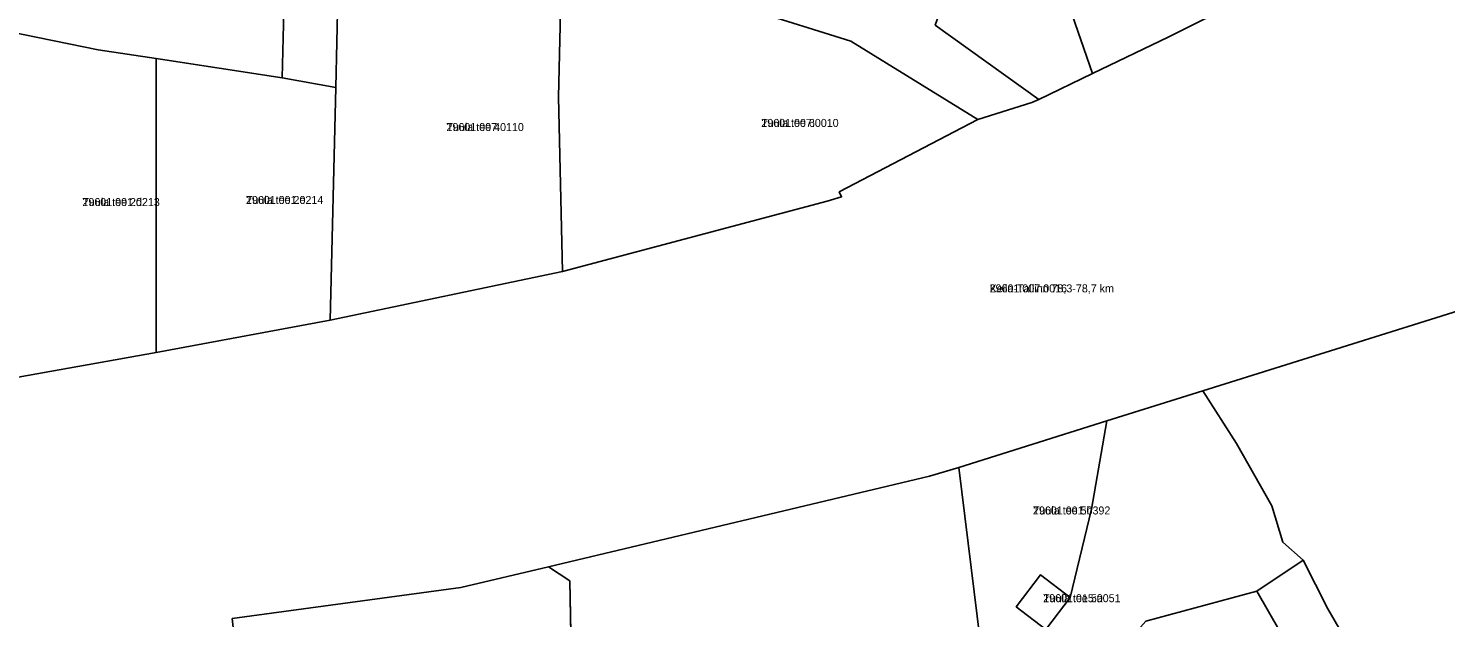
# Model space of a CAD drawing. Extents: x 518839 to 525192, y 6573164 to 6576561.
# Drawn here: x 524522.2 to 524787.8, y 6574299.5 to 6574409.9 of the extents above; entities that cross this region are included whole.
import ezdxf

# ---------------------------------------------------------------- set-up
doc = ezdxf.new("R2010")
doc.units = 0
for name, color, linetype in [('L_AADRESS', 7, 'Continuous'), ('PIIR', 7, 'Continuous'), ('TUNNUS', 7, 'Continuous')]:
    doc.layers.add(name, color=color, linetype=linetype)

msp = doc.modelspace()

# ---------------------------------------------------------------- linework, layer by layer
at = {"layer": 'PIIR'}
for points in [[(524710.7, 6574433.06), (524701.35, 6574436.41), (524703.48, 6574442.58), (524752.09, 6574425.48), (524753.73, 6574417.26), (524735.93, 6574408.31), (524721.62, 6574401.47)], [(524711.59, 6574396.58), (524692.17, 6574410.53), (524701.35, 6574436.41), (524710.7, 6574433.06), (524721.62, 6574401.47)], [(524569.76, 6574400.68), (524570.37, 6574425.69), (524580.41, 6574424.36), (524579.81, 6574398.82)], [(524578.79, 6574355.29), (524579.81, 6574398.82), (524580.41, 6574424.36), (524622.07, 6574418.51), (524621.56, 6574397.04), (524622.34, 6574364.41)], [(524676.36, 6574407.54), (524700.15, 6574392.87), (524674.19, 6574379.29), (524674.63, 6574378.38), (524671.89, 6574377.53), (524622.34, 6574364.41), (524621.56, 6574397.04), (524622.07, 6574418.51), (524657.52, 6574413.39)], [(524518.51, 6574344.28), (524518.5, 6574409.32), (524535.31, 6574405.91), (524546.16, 6574404.26), (524546.14, 6574349.24)], [(524546.14, 6574349.24), (524546.16, 6574404.26), (524569.76, 6574400.68), (524579.81, 6574398.82), (524578.79, 6574355.29)], [(524757.32, 6574313.68), (524755.25, 6574320.46), (524748.62, 6574332.15), (524742.33, 6574342), (524803.74, 6574361.26), (524817.51, 6574365.76), (524818.28, 6574363.86), (524819.99, 6574359.63), (524842.07, 6574311.36), (524849.11, 6574297.12), (524854.77, 6574284.94), (524848.11, 6574281.06), (524835.53, 6574272.95), (524827.49, 6574266.87), (524817.72, 6574259.66), (524804.86, 6574250.61), (524783.72, 6574275.28), (524771.53, 6574291.26), (524765.78, 6574301.17), (524761.13, 6574310.28)], [(524721.44, 6574319.86), (524717.46, 6574303.31), (524711.9, 6574307.56), (524707.37, 6574301.59), (524712.9, 6574297.35), (524702.91, 6574276.51), (524696.62, 6574327.69), (524724.36, 6574336.38)], [(524619.68, 6574309.06), (524691.12, 6574326.02), (524696.62, 6574327.69), (524702.91, 6574276.51), (524701.78, 6574241.63), (524655.29, 6574237.1), (524654.83, 6574244.98), (524646.53, 6574244.88), (524643.9, 6574280.19), (524634.74, 6574287.42), (524624.06, 6574286.46), (524623.93, 6574293.61), (524623.69, 6574306.41)], [(524560.4, 6574299.4), (524603.25, 6574305.18), (524619.68, 6574309.06), (524623.69, 6574306.41), (524624.06, 6574286.46), (524624.27, 6574279.16), (524604.1, 6574276.92), (524605.36, 6574232.04), (524568.45, 6574228.15)], [(524752.47, 6574304.49), (524761.13, 6574310.28), (524765.78, 6574301.17), (524771.53, 6574291.26), (524783.72, 6574275.28), (524804.86, 6574250.61), (524796.76, 6574244.54), (524775.96, 6574268.97), (524763.38, 6574285.46)], [(524711.9, 6574307.56), (524717.46, 6574303.31), (524712.9, 6574297.35), (524707.37, 6574301.59)], [(524758.45, 6574075.08), (524685.85, 6574091.49), (524706.65, 6574149.93), (524716.14, 6574215.55), (524718.22, 6574259.84), (524722.06, 6574288.12), (524731.67, 6574298.88), (524752.47, 6574304.49), (524763.38, 6574285.46), (524763.94, 6574247.94), (524757.99, 6574233.52), (524759.38, 6574223.94), (524761.69, 6574212.15), (524769.27, 6574204.08), (524773.19, 6574198.81), (524777.2, 6574186.81), (524780.96, 6574174.13), (524779.67, 6574161.43), (524773.36, 6574149), (524767.67, 6574140.07), (524757.52, 6574134.15), (524742.35, 6574126.62), (524728.14, 6574113.06), (524743.84, 6574093.15)]]:
    msp.add_lwpolyline(points, close=True, dxfattribs=at)
for points in [[(524377.78, 6574286.88), (524374.42, 6574333.78), (524391.22, 6574334.37), (524426.7, 6574335.33), (524449.29, 6574335.16), (524459.67, 6574335.09), (524482.48, 6574337.78), (524490.84, 6574339.28), (524518.51, 6574344.28), (524546.14, 6574349.24), (524578.79, 6574355.29), (524622.34, 6574364.41), (524671.89, 6574377.53), (524674.63, 6574378.38), (524674.19, 6574379.29), (524700.15, 6574392.87), (524710.26, 6574396.01), (524711.59, 6574396.58), (524721.62, 6574401.47), (524735.93, 6574408.31), (524753.73, 6574417.26), (524778.37, 6574429.72), (524790.19, 6574434.06)], [(524570.37, 6574425.69), (524569.76, 6574400.68), (524546.16, 6574404.26), (524535.31, 6574405.91), (524518.5, 6574409.32)], [(524692.17, 6574410.53), (524711.59, 6574396.58), (524710.26, 6574396.01), (524700.15, 6574392.87), (524676.36, 6574407.54), (524657.52, 6574413.39)], [(524803.74, 6574361.26), (524742.33, 6574342), (524724.36, 6574336.38), (524696.62, 6574327.69), (524691.12, 6574326.02), (524619.68, 6574309.06), (524603.25, 6574305.18), (524560.4, 6574299.4)], [(524712.9, 6574297.35), (524717.46, 6574303.31), (524721.44, 6574319.86), (524724.36, 6574336.38), (524742.33, 6574342), (524748.62, 6574332.15), (524755.25, 6574320.46), (524757.32, 6574313.68), (524761.13, 6574310.28), (524752.47, 6574304.49), (524731.67, 6574298.88)]]:
    msp.add_lwpolyline(points, dxfattribs=at)

# ---------------------------------------------------------------- texts
at = {"layer": 'L_AADRESS'}
for s, p in [('Tuula tee 4', (524600.57, 6574390.69)), ('Tuula tee 6', (524659.57, 6574391.46)), ('Tuula tee 2d', (524532.33, 6574376.64)), ('Tuula tee 2e', (524562.98, 6574377.03)), ('Keila-Tallinn 78,3-78,7 km', (524702.37, 6574360.47)), ('Tuula tee 5b', (524710.49, 6574318.87)), ('Tuula tee 5a', (524712.41, 6574302.44))]:
    msp.add_text(s, height=1.5, dxfattribs=at).set_placement(p)
at = {"layer": 'TUNNUS'}
for s, p in [('29601:007:0110', (524600.57, 6574390.69)), ('29601:007:0010', (524659.57, 6574391.46)), ('29601:001:0213', (524532.33, 6574376.64)), ('29601:001:0214', (524562.98, 6574377.03)), ('29601:007:0016', (524702.37, 6574360.47)), ('29601:001:0392', (524710.49, 6574318.87)), ('29601:015:0051', (524712.41, 6574302.44))]:
    msp.add_text(s, height=1.5, dxfattribs=at).set_placement(p)

doc.saveas('drawing.dxf')
